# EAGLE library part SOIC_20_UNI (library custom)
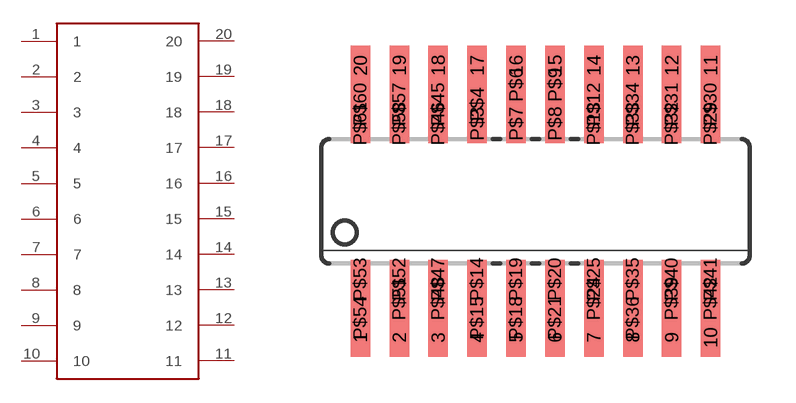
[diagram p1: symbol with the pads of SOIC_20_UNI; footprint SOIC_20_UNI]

Designator prefix -

## SOIC_20_UNI  [SOIC_20_UNI]
1  1
2  2
3  3
4  4
5  5
6  6
7  7
8  8
9  9
10  10
11  11
12  12
13  13
14  14
15  15
16  16
17  17
18  18
19  19
20  20

## Footprint SOIC_20_UNI (pad centres in mm)
Small Outline Package
smd 0.635 x 1.27: 1 -5.715,-4.445; 2 -4.445,-4.445; 3 -3.175,-4.445; 4 -1.905,-4.445; 5 -0.635,-4.445; 6 0.635,-4.445; 7 1.905,-4.445; 8 3.175,-4.445; 9 4.445,-4.445; 10 5.715,-4.445; 11 5.715,4.445; 12 4.445,4.445; 13 3.175,4.445; 14 1.905,4.445; 15 0.635,4.445; 16 -0.635,4.445; 17 -1.905,4.445; 18 -3.175,4.445; 19 -4.445,4.445; 20 -5.715,4.445; P$3 -1.905,2.54; P$4 -1.905,3.175; P$6 -0.635,3.81; P$7 -0.635,2.54; P$8 0.635,2.54; P$9 0.635,3.81; P$12 1.905,3.175; P$13 1.905,2.54; P$14 -1.905,-2.54; P$15 -1.905,-3.81; P$18 -0.635,-3.81; P$19 -0.635,-2.54; P$20 0.635,-2.54; P$21 0.635,-3.81; P$24 1.905,-3.175; P$25 1.905,-2.54; P$29 5.715,2.54; P$30 5.715,3.175; P$31 4.445,3.175; P$32 4.445,2.54; P$33 3.175,2.54; P$34 3.175,3.175; P$35 3.175,-2.54; P$36 3.175,-3.81; P$39 4.445,-3.175; P$40 4.445,-2.54; P$41 5.715,-2.54; P$42 5.715,-3.175; P$45 -3.175,3.175; P$46 -3.175,2.54; P$47 -3.175,-2.54; P$48 -3.175,-3.175; P$51 -4.445,-3.175; P$52 -4.445,-2.54; P$53 -5.715,-2.54; P$54 -5.715,-3.81; P$57 -4.445,3.175; P$58 -4.445,2.54; P$60 -5.715,3.175; P$61 -5.715,2.54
